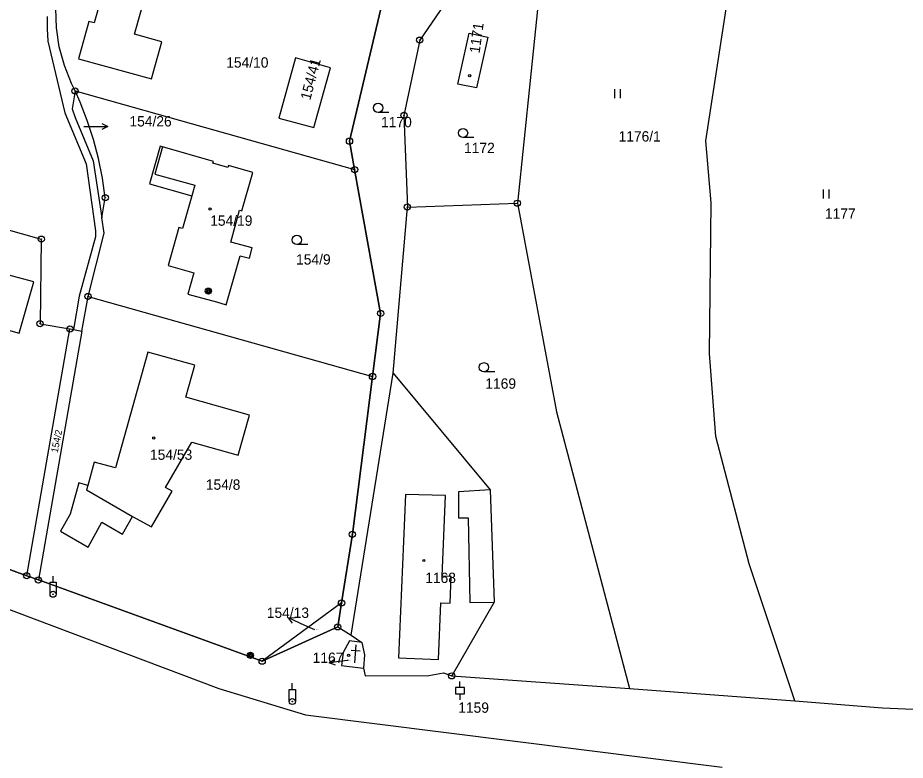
# Model space of a CAD drawing. Extents: x -737240 to -735272, y -1119606 to -1117878.
# Drawn here: x -736684.5 to -736538.4, y -1119465.3 to -1119343.1 of the extents above; entities that cross this region are included whole.
import ezdxf

# ---------------------------------------------------------------- set-up
doc = ezdxf.new("R2010")
doc.units = 0
for name, color, linetype in [('Level 1', 7, 'Continuous'), ('Level 13', 7, 'Continuous'), ('Level 16', 7, 'Continuous'), ('Level 18', 7, 'Continuous'), ('Level 19', 7, 'Continuous'), ('Level 25', 7, 'Continuous'), ('Level 4', 7, 'Continuous')]:
    doc.layers.add(name, color=color, linetype=linetype)

msp = doc.modelspace()

# ---------------------------------------------------------------- linework, layer by layer
at = {"layer": 'Level 1'}
for p, q in [((-736675.06, -1119355.1), (-736629.05, -1119368.06)), ((-736622.7, -1119401.59), (-736620.36, -1119374.23)), ((-736620.36, -1119374.23), (-736602.26, -1119373.59)), ((-736673.92, -1119394.64), (-736672.92, -1119388.95)), ((-736672.92, -1119388.95), (-736626.1, -1119402.13)), ((-736683, -1119434.94), (-736675.89, -1119394.3)), ((-736673.92, -1119394.64), (-736681.09, -1119435.63)), ((-736675.89, -1119394.3), (-736675.32, -1119394.4)), ((-736675.32, -1119394.4), (-736673.92, -1119394.64)), ((-736629.62, -1119444.7), (-736622.7, -1119401.59)), ((-736622.7, -1119401.59), (-736606.77, -1119420.77)), ((-736606.77, -1119420.77), (-736606.09, -1119439.27)), ((-736681.09, -1119435.63), (-736683, -1119434.94)), ((-736644.26, -1119449.01), (-736681.09, -1119435.63)), ((-736631.2, -1119439.41), (-736644.26, -1119449.01)), ((-736606.09, -1119439.27), (-736613.07, -1119451.42)), ((-736631.83, -1119443.36), (-736629.62, -1119444.7)), ((-736629.62, -1119444.7), (-736627.84, -1119445.91)), ((-736613.07, -1119451.42), (-736583.83, -1119453.52)), ((-736583.83, -1119453.52), (-736556.6, -1119455.53))]:
    msp.add_line(p, q, dxfattribs=at)
for points in [[(-736631.83, -1119443.36), (-736631.2, -1119439.41), (-736629.41, -1119428.11), (-736626.1, -1119402.13), (-736624.78, -1119391.75), (-736629.05, -1119368.06), (-736629.89, -1119363.38), (-736624.49, -1119340.65), (-736624.34, -1119337.18), (-736623.89, -1119326.56), (-736620.03, -1119315.17)], [(-736675.06, -1119355.1), (-736675.62, -1119353.87), (-736676.81, -1119350.93), (-736677.65, -1119347.86), (-736678.12, -1119344.72), (-736678.21, -1119341.54), (-736677.94, -1119338.4), (-736677.28, -1119335.26), (-736673.89, -1119323.23)], [(-736652.75, -1119334.65), (-736668.96, -1119330.07), (-736670.7, -1119336.24), (-736669.82, -1119336.48), (-736671.93, -1119343.89), (-736672.77, -1119343.67), (-736674.47, -1119349.8), (-736662.45, -1119353.14), (-736660.76, -1119347.02), (-736665.26, -1119345.76), (-736663.17, -1119338.35), (-736654.48, -1119340.76)], [(-736608.48, -1119332.39), (-736618.33, -1119346.74), (-736620.94, -1119359.13), (-736620.36, -1119374.23)], [(-736608.48, -1119332.39), (-736598.09, -1119333.13), (-736602.26, -1119373.59)], [(-736556.6, -1119455.53), (-736564.1, -1119433), (-736569.62, -1119411.99), (-736570.66, -1119398.36), (-736570.4, -1119373.52), (-736571.28, -1119363.31), (-736566.63, -1119333.35)], [(-736624.34, -1119337.18), (-736624.49, -1119340.65), (-736629.89, -1119363.38), (-736629.05, -1119368.06)], [(-736679.62, -1119342.87), (-736679.66, -1119344.9), (-736679.51, -1119346.94), (-736676.74, -1119358.7), (-736673.24, -1119367.11), (-736671.67, -1119378.15), (-736671.71, -1119379.13), (-736674.36, -1119388.92), (-736675.32, -1119394.4)], [(-736610.21, -1119345.6), (-736607.11, -1119346.28), (-736608.99, -1119354.57), (-736612.04, -1119353.98), (-736610.21, -1119345.6)], [(-736638.8, -1119349.68), (-736641.54, -1119359.58), (-736635.78, -1119361.15), (-736633.02, -1119351.3), (-736638.8, -1119349.68)], [(-736675.06, -1119355.1), (-736675.54, -1119358.04), (-736675.05, -1119359.46), (-736672.07, -1119366.6), (-736670.65, -1119375.98)], [(-736670.65, -1119375.98), (-736670.08, -1119372.7), (-736670.56, -1119369.46), (-736671.21, -1119366.26), (-736672.04, -1119363.1), (-736673.05, -1119359.99), (-736674.23, -1119356.94), (-736675.06, -1119355.1)], [(-736660.66, -1119364.31), (-736661.04, -1119364.2), (-736662.79, -1119370.42), (-736655.86, -1119372.38)], [(-736655.86, -1119372.38), (-736657.37, -1119377.74), (-736657.97, -1119377.57), (-736659.75, -1119383.87), (-736655.51, -1119385.07), (-736656.49, -1119388.55), (-736651.79, -1119389.86), (-736650.16, -1119390.32), (-736647.9, -1119382.24), (-736646.37, -1119382.66), (-736645.9, -1119380.97), (-736649.44, -1119379.99), (-736647.97, -1119374.73), (-736647.59, -1119374.84), (-736645.82, -1119368.54), (-736649.81, -1119367.4), (-736649.9, -1119367.71), (-736652.37, -1119367), (-736652.28, -1119366.7), (-736660.66, -1119364.31)], [(-736629.05, -1119368.06), (-736624.78, -1119391.75), (-736626.1, -1119402.13)], [(-736703.71, -1119373.01), (-736680.61, -1119379.51), (-736680.81, -1119393.44), (-736675.89, -1119394.3)], [(-736821.33, -1119373.76), (-736785.45, -1119389.29), (-736774.88, -1119394.8), (-736760.38, -1119402.35), (-736743.96, -1119409.4), (-736717.18, -1119420.87), (-736691.9, -1119431.7), (-736683, -1119434.94), (-736681.09, -1119435.63), (-736644.26, -1119449.01), (-736631.83, -1119443.36)], [(-736602.26, -1119373.59), (-736595.81, -1119407.93), (-736583.83, -1119453.52)], [(-736672.92, -1119388.95), (-736670.27, -1119378.53), (-736670.65, -1119375.98)], [(-736691.72, -1119392.89), (-736684.23, -1119395.01), (-736681.83, -1119386.55), (-736695.3, -1119382.95), (-736695.84, -1119384.79), (-736702.31, -1119382.97), (-736704.34, -1119390.24), (-736705.2, -1119390.04), (-736707.07, -1119396.74), (-736708.03, -1119396.44), (-736710.21, -1119404.19), (-736704.48, -1119405.8), (-736702.38, -1119398.13), (-736693.85, -1119400.49), (-736691.72, -1119392.89)], [(-736816.52, -1119387.73), (-736763.32, -1119409.91), (-736703.09, -1119434.04), (-736651.38, -1119453.51), (-736637.13, -1119457.85), (-736568.59, -1119466.46)], [(-736665.59, -1119425.17), (-736662.47, -1119426.87), (-736659.1, -1119421.02), (-736660.16, -1119420.41), (-736655.85, -1119412.93), (-736648.21, -1119415.09), (-736646.34, -1119408.5), (-736656.83, -1119405.51), (-736655.35, -1119400.29), (-736663.07, -1119398.12), (-736668.41, -1119417.18), (-736671.91, -1119416.22), (-736672.97, -1119420.09)], [(-736626.1, -1119402.13), (-736629.41, -1119428.11), (-736631.2, -1119439.41)], [(-736672.97, -1119420.09), (-736674.45, -1119419.62), (-736675.88, -1119424.81), (-736677.45, -1119427.59), (-736672.91, -1119430.21), (-736670.63, -1119426.13), (-736667.24, -1119428.07), (-736665.59, -1119425.17)], [(-736683, -1119434.94), (-736691.9, -1119431.7), (-736717.18, -1119420.87)], [(-736631.2, -1119439.41), (-736631.83, -1119443.36), (-736644.26, -1119449.01)], [(-736627.84, -1119445.91), (-736629.88, -1119445.68), (-736630.91, -1119447.57), (-736631.19, -1119449.74), (-736628.09, -1119450.08), (-736627.59, -1119450.13)], [(-736627.84, -1119445.91), (-736627.42, -1119447.95), (-736627.59, -1119450.13)], [(-736627.59, -1119450.13), (-736627.31, -1119451.4), (-736616.85, -1119451.34), (-736614.4, -1119450.94), (-736613.07, -1119451.42)], [(-736556.6, -1119455.53), (-736542.17, -1119456.67), (-736515.54, -1119457.83), (-736488.14, -1119459.31), (-736469.24, -1119453.5)]]:
    msp.add_lwpolyline(points, dxfattribs=at)
at = {"layer": 'Level 13'}
msp.add_lwpolyline([(-736691.06, -1119241.83), (-736667.06, -1119249.16), (-736653.26, -1119253.2), (-736632.34, -1119261.47), (-736619.86, -1119267.96), (-736606.04, -1119273.9), (-736614.86, -1119299.91), (-736616.08, -1119303.51), (-736620.03, -1119315.17), (-736623.89, -1119326.56), (-736624.34, -1119337.18), (-736624.49, -1119340.65), (-736629.89, -1119363.38), (-736629.05, -1119368.06), (-736624.78, -1119391.75), (-736626.1, -1119402.13), (-736629.41, -1119428.11), (-736631.2, -1119439.41), (-736631.83, -1119443.36), (-736644.26, -1119449.01), (-736681.09, -1119435.63), (-736683, -1119434.94), (-736691.9, -1119431.7)], dxfattribs=at)
msp.add_lwpolyline([(-736691.06, -1119241.83), (-736667.06, -1119249.16), (-736653.26, -1119253.2), (-736632.34, -1119261.47), (-736619.86, -1119267.96), (-736606.04, -1119273.9), (-736614.86, -1119299.91), (-736616.08, -1119303.51), (-736620.03, -1119315.17), (-736623.89, -1119326.56), (-736624.34, -1119337.18), (-736624.49, -1119340.65), (-736629.89, -1119363.38), (-736629.05, -1119368.06), (-736624.78, -1119391.75), (-736626.1, -1119402.13), (-736629.41, -1119428.11), (-736631.2, -1119439.41), (-736631.83, -1119443.36), (-736644.26, -1119449.01), (-736681.09, -1119435.63), (-736683, -1119434.94), (-736691.9, -1119431.7)], dxfattribs=at)
at = {"layer": 'Level 16'}
for points in [[(-736673.6, -1119360.96), (-736672.65, -1119360.96), (-736669.65, -1119360.96)], [(-736670.65, -1119360.46), (-736669.65, -1119360.96), (-736670.65, -1119361.46)], [(-736639.249, -1119442.744), (-736639.955, -1119441.877), (-736638.838, -1119441.832)], [(-736635.58, -1119443.85), (-736637.22, -1119443.11), (-736639.955, -1119441.877)], [(-736632.189, -1119449.648), (-736633.25, -1119449.294), (-736632.331, -1119448.658)], [(-736630.1, -1119448.84), (-736630.28, -1119448.87), (-736633.25, -1119449.294)]]:
    msp.add_lwpolyline(points, dxfattribs=at)
at = {"layer": 'Level 25'}
for p, q in [((-736586.297, -1119354.825), (-736586.297, -1119356.325)), ((-736585.275, -1119356.325), (-736585.275, -1119354.825)), ((-736623.398, -1119358.65), (-736625.18, -1119358.65)), ((-736609.428, -1119362.79), (-736611.21, -1119362.79)), ((-736551.957, -1119371.345), (-736551.957, -1119372.845)), ((-736550.935, -1119372.845), (-736550.935, -1119371.345)), ((-736636.768, -1119380.39), (-736638.55, -1119380.39)), ((-736605.988, -1119401.36), (-736607.77, -1119401.36)), ((-736678.67, -1119435.99), (-736678.67, -1119434.99)), ((-736629, -1119449.29), (-736628.814, -1119446.296)), ((-736628.128, -1119447.34), (-736629.625, -1119447.248)), ((-736639.3, -1119453.65), (-736639.3, -1119452.65)), ((-736611.72, -1119453.36), (-736611.72, -1119452.36)), ((-736611.72, -1119454.36), (-736611.72, -1119455.36))]:
    msp.add_line(p, q, dxfattribs=at)
for points in [[(-736679.17, -1119437.99), (-736679.17, -1119435.99), (-736678.17, -1119435.99), (-736678.17, -1119437.99)], [(-736639.8, -1119455.65), (-736639.8, -1119453.65), (-736638.8, -1119453.65), (-736638.8, -1119455.65)]]:
    msp.add_lwpolyline(points, dxfattribs=at)
msp.add_lwpolyline([(-736612.47, -1119454.36), (-736610.97, -1119454.36), (-736610.97, -1119453.36), (-736612.47, -1119453.36)], close=True, dxfattribs=at)
for centre, radius in [((-736678.67, -1119437.99), 0.5), ((-736678.67, -1119437.99), 0.05), ((-736639.3, -1119455.65), 0.5), ((-736639.3, -1119455.65), 0.05)]:
    msp.add_circle(centre, radius, dxfattribs=at)
for centre, major_axis, ratio in [((-736618.33, -1119346.74), (0.516, 0), 0.9848078), ((-736618.33, -1119346.74), (0.0375, 0), 0.9848078), ((-736610.11, -1119352.59), (0.18, 0), 0.9848078), ((-736675.06, -1119355.1), (0.516, 0), 0.9848078), ((-736675.06, -1119355.1), (0.0375, 0), 0.9848078), ((-736625.18, -1119357.894), (0.764, 0), 0.9894236), ((-736620.94, -1119359.13), (0.516, 0), 0.9848078), ((-736620.94, -1119359.13), (0.0375, 0), 0.9848078), ((-736611.21, -1119362.034), (0.764, 0), 0.9894236), ((-736629.89, -1119363.38), (0.516, 0), 0.9848078), ((-736629.89, -1119363.38), (0.0375, 0), 0.9848078), ((-736629.05, -1119368.06), (0.516, 0), 0.9848078), ((-736629.05, -1119368.06), (0.0375, 0), 0.9848078), ((-736670.08, -1119372.7), (0.516, 0), 0.9848078), ((-736670.08, -1119372.7), (0.0375, 0), 0.9848078), ((-736602.26, -1119373.59), (0.516, 0), 0.9848078), ((-736652.83, -1119374.56), (0.18, 0), 0.9848078), ((-736620.36, -1119374.23), (0.516, 0), 0.9848078), ((-736620.36, -1119374.23), (0.0375, 0), 0.9848078), ((-736602.26, -1119373.59), (0.0375, 0), 0.9848078), ((-736680.61, -1119379.51), (0.516, 0), 0.9848078), ((-736638.55, -1119379.634), (0.764, 0), 0.9894236), ((-736680.61, -1119379.51), (0.0375, 0), 0.9848078), ((-736653.11, -1119388.07), (0.516, 0), 0.9848078), ((-736653.11, -1119388.07), (0.309, 0), 0.9848078), ((-736653.11, -1119388.07), (0.155, 0), 0.9848078), ((-736672.92, -1119388.95), (0.516, 0), 0.9848078), ((-736672.92, -1119388.95), (0.0375, 0), 0.9848078), ((-736624.78, -1119391.75), (0.516, 0), 0.9848078), ((-736624.78, -1119391.75), (0.0375, 0), 0.9848078), ((-736680.81, -1119393.44), (0.516, 0), 0.9848078), ((-736680.81, -1119393.44), (0.0375, 0), 0.9848078), ((-736675.89, -1119394.3), (0.516, 0), 0.9848078), ((-736675.89, -1119394.3), (0.0375, 0), 0.9848078), ((-736607.77, -1119400.604), (0.764, 0), 0.9894236), ((-736626.1, -1119402.13), (0.516, 0), 0.9848078), ((-736626.1, -1119402.13), (0.0375, 0), 0.9848078), ((-736662.1, -1119412.25), (0.18, 0), 0.9848078), ((-736629.41, -1119428.11), (0.516, 0), 0.9848078), ((-736629.41, -1119428.11), (0.0375, 0), 0.9848078), ((-736617.65, -1119432.42), (0.18, 0), 0.9848078), ((-736683, -1119434.94), (0.516, 0), 0.9848078), ((-736683, -1119434.94), (0.0375, 0), 0.9848078), ((-736681.09, -1119435.63), (0.516, 0), 0.9848078), ((-736681.09, -1119435.63), (0.0375, 0), 0.9848078), ((-736631.2, -1119439.41), (0.516, 0), 0.9848078), ((-736631.2, -1119439.41), (0.0375, 0), 0.9848078), ((-736631.83, -1119443.36), (0.516, 0), 0.9848078), ((-736631.83, -1119443.36), (0.0375, 0), 0.9848078), ((-736646.21, -1119448.03), (0.516, 0), 0.9848078), ((-736646.21, -1119448.03), (0.309, 0), 0.9848078), ((-736646.21, -1119448.03), (0.155, 0), 0.9848078), ((-736630.04, -1119448.03), (0.18, 0), 0.9848078), ((-736644.26, -1119449.01), (0.516, 0), 0.9848078), ((-736644.26, -1119449.01), (0.0375, 0), 0.9848078), ((-736613.07, -1119451.42), (0.516, 0), 0.9848078), ((-736613.07, -1119451.42), (0.0375, 0), 0.9848078)]:
    msp.add_ellipse(centre, major_axis=major_axis, ratio=ratio, dxfattribs=at)
at = {"layer": 'Level 4'}
for points in [[(-736660.66, -1119364.31), (-736661.92, -1119368.8), (-736655.37, -1119370.65), (-736655.86, -1119372.38)], [(-736672.97, -1119420.09), (-736673.16, -1119420.77), (-736665.59, -1119425.17)], [(-736613.34, -1119439.43), (-736613.15, -1119435.07), (-736614.67, -1119435), (-736614.12, -1119421.7), (-736620.66, -1119421.55), (-736621.83, -1119448.44), (-736615.23, -1119448.74), (-736614.85, -1119439.38), (-736613.34, -1119439.43)], [(-736606.77, -1119420.77), (-736611.97, -1119421.14), (-736611.98, -1119425.42), (-736610.36, -1119425.39), (-736610.08, -1119439.37), (-736606.09, -1119439.27)]]:
    msp.add_lwpolyline(points, dxfattribs=at)

# ---------------------------------------------------------------- texts
at = {"layer": 'Level 16'}
for s, p in [('154/26', (-736666.1, -1119360.96)), ('154/13', (-736643.5, -1119441.88)), ('1167', (-736635.95, -1119449.29))]:
    msp.add_text(s, height=1.7, dxfattribs=at).set_placement(p)
at = {"layer": 'Level 18'}
for s, height, p in [('154/10', 1.7, (-736650.18, -1119351.27)), ('1170', 1.7, (-736624.7, -1119361.09)), ('154/26', 0.1, (-736673.45, -1119360.96)), ('1176/1', 1.7, (-736585.62, -1119363.44)), ('1172', 1.7, (-736611.04, -1119365.34)), ('1177', 1.7, (-736551.65, -1119376.15)), ('154/9', 1.7, (-736638.685, -1119383.7)), ('1169', 1.7, (-736607.54, -1119404.14)), ('154/8', 1.7, (-736653.535, -1119420.78)), ('154/13', 0.1, (-736635.43, -1119443.85)), ('1159', 1.7, (-736612, -1119457.5))]:
    msp.add_text(s, height=height, dxfattribs=at).set_placement(p)
for s, height, rotation, p in [('154/41', 1.7, 75.31803, (-736636.354, -1119356.723)), ('154/2', 1.14, 78.42483, (-736677.914, -1119414.754))]:
    msp.add_text(s, height=height, rotation=rotation, dxfattribs=at).set_placement(p)
at = {"layer": 'Level 19'}
msp.add_text('1171', height=1.7, rotation=82.02672, dxfattribs=at).set_placement((-736608.495, -1119348.986))
for s, height, p in [('154/19', 1.7, (-736652.815, -1119377.31)), ('154/53', 1.7, (-736662.72, -1119415.85)), ('1168', 1.7, (-736617.435, -1119436.13)), ('1167', 0.1, (-736629.975, -1119448.84))]:
    msp.add_text(s, height=height, dxfattribs=at).set_placement(p)

doc.saveas('drawing.dxf')
